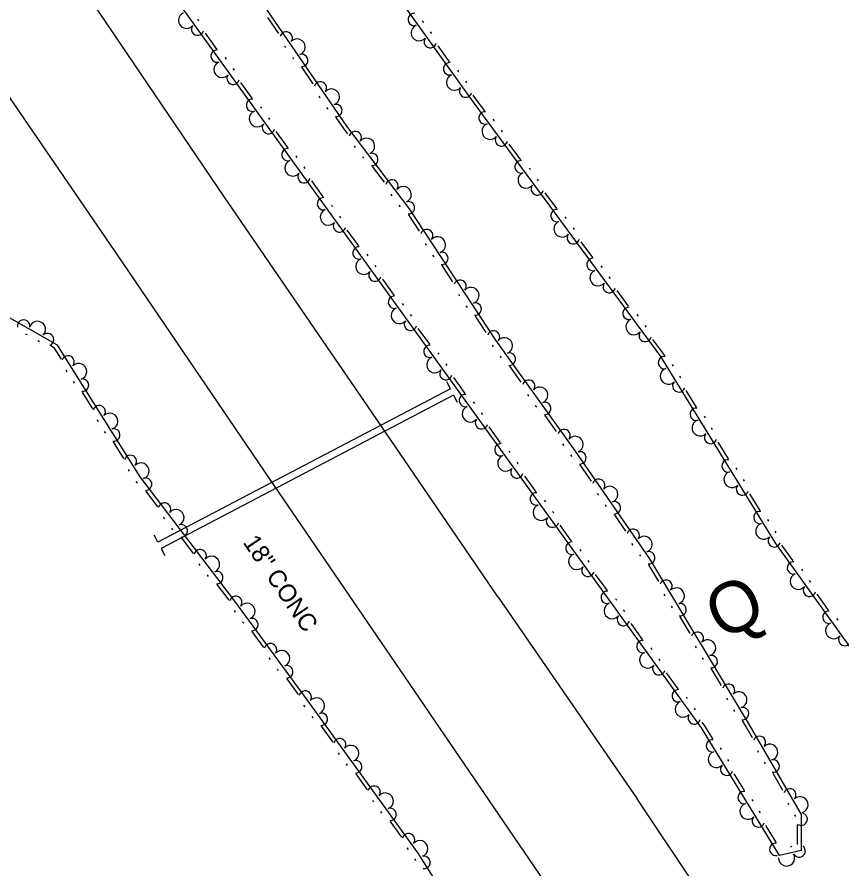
# Model space of a CAD drawing. Extents: x 2030130 to 2036320, y 723205 to 762423.
# Drawn here: x 2033217 to 2033389.9, y 761306.1 to 761484.7 of the extents above; entities that cross this region are included whole.
import ezdxf

# ---------------------------------------------------------------- set-up
doc = ezdxf.new("R2010")
doc.units = 0
for name, color, linetype in [('Draft_Station Labels Major', 7, 'Continuous'), ('Draft_Station Tics Major', 7, 'Continuous'), ('Draft_Station Tics Minor', 7, 'Continuous'), ('Old_Level_15', 7, 'Continuous'), ('Old_Level_26', 7, 'Continuous')]:
    doc.layers.add(name, color=color, linetype=linetype)

msp = doc.modelspace()

# ---------------------------------------------------------------- linework, layer by layer
at = {"layer": 'Draft_Station Labels Major'}
for p, q in [((2033317.86, 761363.04), (2033346.96, 761320.77)), ((2033297.27, 761347.85), (2033325.26, 761306.74))]:
    msp.add_line(p, q, dxfattribs=at)
for points in [[(2033317.86, 761363.04), (2033290.43, 761403.19), (2033260.47, 761446.88), (2033232.75, 761487.83), (2033204.6, 761528.87), (2033176.73, 761570.42), (2033148.96, 761611.47), (2033120.54, 761652.92), (2033093.45, 761693.44), (2033064.45, 761735.88), (2033037.38, 761775.77), (2033009.06, 761817.74)], [(2032987.95, 761803.12), (2033043.65, 761720.79), (2033056.64, 761702.34), (2033057.8, 761696.58), (2033076.72, 761668.89), (2033082.75, 761662.9), (2033099.45, 761638.44), (2033127.47, 761597.33), (2033155.33, 761556.18), (2033183.52, 761515.12), (2033211.27, 761473.78), (2033239.33, 761432.83), (2033268.78, 761389.51), (2033297.27, 761347.85)], [(2033712.22, 760786.66), (2033683.84, 760828.02), (2033655.87, 760868.99), (2033628.83, 760908.43), (2033600.16, 760950.82), (2033571.79, 760992.23), (2033543.75, 761033.03), (2033515.6, 761074.29), (2033487.47, 761115.18), (2033459.15, 761156.4), (2033430.9, 761197.59), (2033402.93, 761238.74), (2033380.71, 761271.71), (2033360.2, 761301.06), (2033346.96, 761320.77)], [(2033325.26, 761306.74), (2033353.27, 761265.49), (2033381.46, 761224.47), (2033409.65, 761183.47), (2033437.67, 761142.45), (2033465.74, 761101.32), (2033493.99, 761060.24), (2033522.13, 761019.11), (2033550.25, 760977.98), (2033578.36, 760936.85), (2033606.28, 760895.5), (2033634.33, 760854.29), (2033662.48, 760813.18), (2033690.27, 760771.87)]]:
    msp.add_lwpolyline(points, dxfattribs=at)
at = {"layer": 'Draft_Station Tics Major'}
for points in [[(2033068.77, 761781.86), (2033086.33, 761752.31), (2033109.9, 761713.34), (2033142.91, 761665.44), (2033169.42, 761629.65), (2033193.38, 761594), (2033213.28, 761565.74), (2033225.71, 761547.14), (2033246.82, 761520.6), (2033267.65, 761488.73), (2033286.08, 761461.77), (2033299.18, 761444.47), (2033317.3, 761416.96), (2033333.98, 761393.69), (2033349.54, 761371.11), (2033370.47, 761336.34), (2033381.34, 761317.53), (2033381.31, 761309.98), (2033376.82, 761308.9), (2033360.46, 761335.66), (2033268.79, 761462.78), (2033184.77, 761579.48), (2033107.4, 761688.4), (2033049.51, 761771.21)], [(2033399.47, 761341.65), (2033376.06, 761374.31), (2033351.9, 761413.52), (2033313, 761466.36), (2033285.32, 761505.1)], [(2033255.14, 761483.84), (2033254.9, 761484.18)], [(2033269.5, 761484.57), (2033271.81, 761481.18)], [(2033302.24, 761483.54), (2033302, 761483.87)], [(2033258.88, 761477.95), (2033256.49, 761481.27)], [(2033303.91, 761481.2), (2033303.67, 761481.54)], [(2033273.09, 761478.58), (2033273.33, 761478.24)], [(2033307.63, 761475.29), (2033305.24, 761478.63)], [(2033260.89, 761475.86), (2033260.65, 761476.19)], [(2033274.71, 761476.21), (2033274.95, 761475.87)], [(2033262.57, 761473.53), (2033262.33, 761473.86)], [(2033276.67, 761474.07), (2033278.99, 761470.69)], [(2033309.63, 761473.2), (2033309.39, 761473.53)], [(2033266.31, 761467.63), (2033263.92, 761470.96)], [(2033311.3, 761470.86), (2033311.06, 761471.19)], [(2033280.27, 761468.09), (2033280.5, 761467.75)], [(2033315.04, 761464.98), (2033313.67, 761466.84), (2033312.63, 761468.29)], [(2033268.32, 761465.54), (2033268.08, 761465.87)], [(2033281.89, 761465.72), (2033282.12, 761465.38)], [(2033270, 761463.21), (2033269.79, 761463.5), (2033269.76, 761463.54)], [(2033283.85, 761463.58), (2033285.41, 761461.29), (2033286.24, 761460.2)], [(2033317.07, 761462.91), (2033316.83, 761463.24)], [(2033273.74, 761457.32), (2033271.34, 761460.64)], [(2033318.77, 761460.6), (2033318.53, 761460.93)], [(2033287.65, 761457.66), (2033287.89, 761457.33)], [(2033322.58, 761454.74), (2033320.15, 761458.04)], [(2033275.75, 761455.23), (2033275.52, 761455.56)], [(2033289.38, 761455.37), (2033289.63, 761455.05)], [(2033277.43, 761452.9), (2033277.19, 761453.23)], [(2033291.44, 761453.33), (2033293.92, 761450.06)], [(2033324.61, 761452.67), (2033324.37, 761453)], [(2033281.18, 761447), (2033278.78, 761450.33)], [(2033326.31, 761450.36), (2033326.07, 761450.69)], [(2033295.32, 761447.53), (2033295.57, 761447.2)], [(2033330.11, 761444.5), (2033327.68, 761447.8)], [(2033283.19, 761444.92), (2033282.95, 761445.25)], [(2033297.06, 761445.24), (2033297.3, 761444.91)], [(2033299.03, 761443.21), (2033301.29, 761439.78)], [(2033284.87, 761442.59), (2033284.63, 761442.92)], [(2033332.15, 761442.43), (2033331.9, 761442.76)], [(2033288.62, 761436.69), (2033286.22, 761440.02)], [(2033333.85, 761440.12), (2033333.61, 761440.45)], [(2033302.53, 761437.16), (2033302.75, 761436.82)], [(2033337.65, 761434.26), (2033335.22, 761437.57)], [(2033290.63, 761434.6), (2033290.39, 761434.94)], [(2033304.11, 761434.76), (2033304.33, 761434.42)], [(2033292.31, 761432.27), (2033292.07, 761432.61)], [(2033306.03, 761432.59), (2033308.28, 761429.17)], [(2033339.68, 761432.19), (2033339.44, 761432.53)], [(2033296.05, 761426.38), (2033293.65, 761429.71)], [(2033341.39, 761429.88), (2033341.14, 761430.21)], [(2033345.19, 761424.03), (2033342.76, 761427.33)], [(2033309.52, 761426.54), (2033309.75, 761426.2)], [(2033298.06, 761424.29), (2033297.82, 761424.62)], [(2033311.1, 761424.14), (2033311.33, 761423.8)], [(2033373.93, 761191.17), (2033356.73, 761221.91), (2033337.95, 761251.98), (2033321.33, 761277.24), (2033301.07, 761309.44), (2033278.03, 761341.3), (2033262.68, 761362.2), (2033242.79, 761388.29), (2033225.48, 761415.9), (2033212.95, 761422.98)], [(2033299.74, 761421.96), (2033299.5, 761422.3)], [(2033313.02, 761421.97), (2033315.28, 761418.55)], [(2033347.22, 761421.96), (2033346.98, 761422.29)], [(2033348.92, 761419.65), (2033348.68, 761419.98)], [(2033219.23, 761418.02), (2033218.87, 761418.22)], [(2033303.49, 761416.07), (2033301.09, 761419.4)], [(2033221.72, 761416.61), (2033221.37, 761416.81)], [(2033352.75, 761413.72), (2033352.59, 761413.98), (2033350.29, 761417.09)], [(2033226.35, 761412.97), (2033224.9, 761415.29), (2033224.07, 761415.76)], [(2033316.56, 761415.9), (2033316.79, 761415.56)], [(2033305.5, 761413.98), (2033305.26, 761414.31)], [(2033318.23, 761413.56), (2033318.47, 761413.23)], [(2033307.18, 761411.65), (2033306.94, 761411.98)], [(2033320.23, 761411.47), (2033322.62, 761408.13)], [(2033354.6, 761411.49), (2033354.39, 761411.84)], [(2033227.53, 761410.32), (2033227.31, 761410.67)], [(2033356.11, 761409.05), (2033355.89, 761409.4)], [(2033229.05, 761407.89), (2033228.83, 761408.24)], [(2033310.92, 761405.76), (2033308.53, 761409.08)], [(2033232.89, 761402.55), (2033230.71, 761406.02)], [(2033359.41, 761402.9), (2033357.26, 761406.39)], [(2033312.93, 761403.67), (2033312.69, 761404)], [(2033323.96, 761405.56), (2033324.2, 761405.23)], [(2033325.63, 761403.23), (2033325.87, 761402.89)], [(2033234.06, 761399.9), (2033233.84, 761400.25)], [(2033314.61, 761401.34), (2033314.37, 761401.67)], [(2033327.64, 761401.13), (2033330.03, 761397.8)], [(2033361.27, 761400.67), (2033361.05, 761401.02)], [(2033318.36, 761395.45), (2033315.96, 761398.77)], [(2033362.77, 761398.22), (2033362.56, 761398.57)], [(2033235.59, 761397.46), (2033235.37, 761397.81)], [(2033239.42, 761392.12), (2033237.24, 761395.6)], [(2033331.36, 761395.23), (2033331.6, 761394.89)], [(2033366.08, 761392.07), (2033363.93, 761395.56)], [(2033320.37, 761393.36), (2033320.13, 761393.69)], [(2033322.05, 761391.03), (2033321.81, 761391.36)], [(2033333.02, 761392.91), (2033333.25, 761392.57)], [(2033240.6, 761389.47), (2033240.38, 761389.82)], [(2033334.99, 761390.78), (2033337.32, 761387.4)], [(2033367.94, 761389.84), (2033367.72, 761390.19)], [(2033325.8, 761385.13), (2033323.4, 761388.46)], [(2033369.44, 761387.4), (2033369.23, 761387.75)], [(2033242.24, 761386.99), (2033241.99, 761387.31)], [(2033246.54, 761382.02), (2033244.06, 761385.28)], [(2033338.61, 761384.81), (2033338.84, 761384.47)], [(2033372.75, 761381.25), (2033370.6, 761384.74)], [(2033327.81, 761383.05), (2033327.57, 761383.38)], [(2033340.24, 761382.44), (2033340.47, 761382.1)], [(2033329.49, 761380.72), (2033329.25, 761381.05)], [(2033247.96, 761379.48), (2033247.71, 761379.81)], [(2033342.2, 761380.31), (2033344.53, 761376.93)], [(2033374.6, 761379.02), (2033374.39, 761379.37)], [(2033249.7, 761377.2), (2033249.45, 761377.53)], [(2033333.23, 761374.82), (2033330.83, 761378.15)], [(2033254, 761372.23), (2033251.52, 761375.49)], [(2033376.11, 761376.58), (2033375.89, 761376.92)], [(2033345.82, 761374.34), (2033346.05, 761374)], [(2033379.68, 761370.67), (2033377.29, 761374)], [(2033335.25, 761372.73), (2033335.01, 761373.07)], [(2033347.45, 761371.97), (2033347.68, 761371.64)], [(2033255.42, 761369.7), (2033255.17, 761370.03)], [(2033336.92, 761370.4), (2033336.68, 761370.74)], [(2033349.34, 761369.85), (2033351.46, 761366.34)], [(2033381.69, 761368.57), (2033381.45, 761368.91)], [(2033257.16, 761367.42), (2033256.91, 761367.74)], [(2033340.67, 761364.51), (2033338.27, 761367.84)], [(2033383.36, 761366.24), (2033383.12, 761366.57)], [(2033261.46, 761362.45), (2033258.97, 761365.71)], [(2033342.68, 761362.42), (2033342.44, 761362.75)], [(2033352.58, 761363.67), (2033352.8, 761363.32)], [(2033387.09, 761360.33), (2033384.7, 761363.67)], [(2033354.07, 761361.21), (2033354.28, 761360.86)], [(2033262.83, 761359.91), (2033262.59, 761360.24)], [(2033344.36, 761360.09), (2033344.12, 761360.43)], [(2033264.53, 761357.6), (2033264.29, 761357.93)], [(2033348.1, 761354.2), (2033345.71, 761357.53)], [(2033355.9, 761358.96), (2033358.01, 761355.45)], [(2033389.09, 761358.24), (2033388.85, 761358.57)], [(2033268.75, 761352.55), (2033266.32, 761355.86)], [(2033350.12, 761352.11), (2033349.88, 761352.44)], [(2033359.14, 761352.78), (2033359.35, 761352.43)], [(2033270.12, 761349.99), (2033269.87, 761350.33)], [(2033360.62, 761350.32), (2033360.83, 761349.97)], [(2033351.8, 761349.78), (2033351.55, 761350.12)], [(2033271.82, 761347.68), (2033271.57, 761348.01)], [(2033355.54, 761343.89), (2033353.14, 761347.21)], [(2033362.45, 761348.07), (2033364.57, 761344.56)], [(2033276.03, 761342.64), (2033273.6, 761345.94)], [(2033357.55, 761341.8), (2033357.31, 761342.13)], [(2033365.7, 761341.89), (2033365.91, 761341.53)], [(2033277.39, 761340.08), (2033277.15, 761340.42)], [(2033359.23, 761339.47), (2033358.99, 761339.8)], [(2033279.07, 761337.76), (2033278.83, 761338.09)], [(2033367.18, 761339.43), (2033367.39, 761339.08)], [(2033283.25, 761332.68), (2033280.85, 761336)], [(2033362.81, 761333.39), (2033361.15, 761336.12), (2033360.58, 761336.9)], [(2033369.01, 761337.18), (2033369.77, 761335.93), (2033371.08, 761333.65)], [(2033364.66, 761331.15), (2033364.45, 761331.5)], [(2033372.16, 761330.96), (2033372.36, 761330.61)], [(2033284.6, 761330.11), (2033284.36, 761330.45)], [(2033366.16, 761328.71), (2033365.94, 761329.06)], [(2033286.28, 761327.79), (2033286.04, 761328.12)], [(2033373.59, 761328.48), (2033373.8, 761328.12)], [(2033290.46, 761322.71), (2033288.06, 761326.03)], [(2033369.44, 761322.54), (2033367.3, 761326.04)], [(2033375.39, 761326.2), (2033377.44, 761322.65)], [(2033291.81, 761320.15), (2033291.57, 761320.48)], [(2033371.29, 761320.31), (2033371.08, 761320.66)], [(2033378.52, 761319.95), (2033378.72, 761319.6)], [(2033293.49, 761317.82), (2033293.25, 761318.15)], [(2033372.79, 761317.86), (2033372.57, 761318.21)], [(2033379.95, 761317.47), (2033380.16, 761317.11)], [(2033297.67, 761312.74), (2033295.27, 761316.07)], [(2033376.07, 761311.7), (2033373.93, 761315.2)], [(2033380.51, 761315.3), (2033380.5, 761311.2)], [(2033299.02, 761310.18), (2033298.78, 761310.51)], [(2033379.42, 761310.79), (2033379.02, 761310.69)], [(2033300.6, 761307.88), (2033300.38, 761308.22)]]:
    msp.add_lwpolyline(points, dxfattribs=at)
for centre, radius, start, end in [((2033252.52, 761483.98), 1.69, 111.7161, 319.7886), ((2033300.28, 761484.16), 1.3, 86.3189, 287.1155), ((2033254.86, 761482.13), 1.3, 144.1873, 344.9839), ((2033301.29, 761481.35), 1.69, 111.5142, 319.5867), ((2033273.42, 761480.29), 1.3, 322.7904, 163.5869), ((2033275.71, 761478.38), 1.69, 290.3192, 138.3917), ((2033303.62, 761479.49), 1.3, 143.9854, 344.7819), ((2033258.94, 761476.47), 1.3, 86.5208, 287.3174), ((2033259.95, 761473.66), 1.69, 111.7161, 319.7886), ((2033276.66, 761475.55), 1.3, 265.1239, 105.9205), ((2033307.68, 761473.82), 1.3, 86.3189, 287.1155), ((2033262.29, 761471.81), 1.3, 144.1873, 344.9839), ((2033308.68, 761471), 1.69, 111.5142, 319.5867), ((2033280.59, 761469.8), 1.3, 322.7904, 163.5869), ((2033311.01, 761469.14), 1.3, 143.9854, 344.7819), ((2033282.89, 761467.89), 1.69, 290.3192, 138.3917), ((2033266.36, 761466.15), 1.3, 86.5208, 287.3174), ((2033283.83, 761465.06), 1.3, 265.1239, 105.9205), ((2033267.38, 761463.34), 1.69, 111.7161, 319.7886), ((2033315.11, 761463.5), 1.3, 87.1294, 287.926), ((2033269.72, 761461.49), 1.3, 144.2321, 345.0287), ((2033316.15, 761460.7), 1.69, 112.3247, 320.3972), ((2033287.88, 761459.39), 1.3, 325.5863, 166.3829), ((2033290.27, 761457.59), 1.69, 293.1152, 141.1876), ((2033318.51, 761458.88), 1.3, 144.7959, 345.5925), ((2033273.8, 761455.84), 1.3, 86.5657, 287.3622), ((2033291.35, 761454.81), 1.3, 267.9199, 108.7164), ((2033274.81, 761453.03), 1.69, 111.7609, 319.8334), ((2033322.65, 761453.26), 1.3, 87.1294, 287.926), ((2033323.69, 761450.46), 1.69, 112.3247, 320.3972), ((2033277.16, 761451.18), 1.3, 144.2321, 345.0287), ((2033295.56, 761449.25), 1.3, 325.5863, 166.3829), ((2033297.95, 761447.46), 1.69, 293.1152, 141.1876), ((2033326.05, 761448.64), 1.3, 144.7959, 345.5925), ((2033281.23, 761445.53), 1.3, 86.5657, 287.3622), ((2033299.03, 761444.68), 1.3, 267.9199, 108.7164), ((2033282.25, 761442.72), 1.69, 111.7609, 319.8334), ((2033330.18, 761443.03), 1.3, 87.1294, 287.926), ((2033284.59, 761440.87), 1.3, 144.2321, 345.0287), ((2033331.22, 761440.23), 1.69, 112.3247, 320.3972), ((2033302.88, 761438.86), 1.3, 321.8089, 162.6054), ((2033305.14, 761436.92), 1.69, 289.3377, 137.4102), ((2033333.59, 761438.4), 1.3, 144.7959, 345.5925), ((2033288.67, 761435.21), 1.3, 86.5657, 287.3622), ((2033306.04, 761434.07), 1.3, 264.1424, 104.939), ((2033289.68, 761432.41), 1.69, 111.7609, 319.8334), ((2033337.72, 761432.79), 1.3, 87.1294, 287.926), ((2033292.03, 761430.56), 1.3, 144.2321, 345.0287), ((2033338.76, 761429.99), 1.69, 112.3247, 320.3972), ((2033309.87, 761428.25), 1.3, 321.8089, 162.6054), ((2033341.12, 761428.16), 1.3, 144.7959, 345.5925), ((2033312.14, 761426.3), 1.69, 289.3377, 137.4102), ((2033296.11, 761424.9), 1.3, 86.5657, 287.3622), ((2033297.12, 761422.09), 1.69, 111.7609, 319.8334), ((2033313.03, 761423.45), 1.3, 264.1424, 104.939), ((2033345.26, 761422.55), 1.3, 87.1294, 287.926), ((2033218.4, 761419.9), 1.3, 348.9505, 189.7471), ((2033221.3, 761419.2), 1.69, 316.4793, 164.5518), ((2033299.46, 761420.25), 1.3, 144.2321, 345.0287), ((2033346.3, 761419.75), 1.69, 112.3247, 320.3972), ((2033223.4, 761417.07), 1.3, 291.2841, 132.0806), ((2033316.87, 761417.63), 1.3, 321.8089, 162.6054), ((2033348.66, 761417.93), 1.3, 144.7959, 345.5925), ((2033319.18, 761415.76), 1.69, 291.5846, 139.6571), ((2033303.54, 761414.59), 1.3, 86.5657, 287.3622), ((2033227.7, 761412.36), 1.3, 320.5276, 161.3242), ((2033304.56, 761411.78), 1.69, 111.7609, 319.8334), ((2033320.18, 761412.95), 1.3, 266.3894, 107.1859), ((2033352.69, 761412.24), 1.3, 82.4032, 283.1998), ((2033229.92, 761410.37), 1.69, 288.0564, 136.1289), ((2033353.5, 761409.37), 1.69, 107.5985, 315.671), ((2033306.9, 761409.93), 1.3, 144.2321, 345.0287), ((2033230.75, 761407.5), 1.3, 262.8612, 103.6577), ((2033324.24, 761407.28), 1.3, 324.0558, 164.8524), ((2033355.7, 761407.35), 1.3, 140.0697, 340.8662), ((2033326.58, 761405.42), 1.69, 291.5846, 139.6571), ((2033310.98, 761404.28), 1.3, 86.5657, 287.3622), ((2033327.59, 761402.61), 1.3, 266.3894, 107.1859), ((2033234.23, 761401.94), 1.3, 320.5276, 161.3242), ((2033311.99, 761401.47), 1.69, 111.7609, 319.8334), ((2033359.36, 761401.42), 1.3, 82.4032, 283.1998), ((2033236.45, 761399.94), 1.69, 288.0564, 136.1289), ((2033314.34, 761399.62), 1.3, 144.2321, 345.0287), ((2033360.17, 761398.54), 1.69, 107.5985, 315.671), ((2033237.28, 761397.08), 1.3, 262.8612, 103.6577), ((2033331.65, 761396.94), 1.3, 324.0558, 164.8524), ((2033333.99, 761395.09), 1.69, 291.5846, 139.6571), ((2033362.37, 761396.53), 1.3, 140.0697, 340.8662), ((2033318.41, 761393.97), 1.3, 86.5657, 287.3622), ((2033334.97, 761392.26), 1.3, 265.3423, 106.1389), ((2033240.77, 761391.52), 1.3, 320.5276, 161.3242), ((2033319.43, 761391.16), 1.69, 111.7609, 319.8334), ((2033366.03, 761390.59), 1.3, 82.4032, 283.1998), ((2033242.99, 761389.52), 1.69, 288.0564, 136.1289), ((2033321.77, 761389.31), 1.3, 144.2321, 345.0287), ((2033243.96, 761386.75), 1.3, 268.0802, 108.8768), ((2033338.92, 761386.52), 1.3, 323.0088, 163.8053), ((2033366.84, 761387.72), 1.69, 107.5985, 315.671), ((2033341.23, 761384.62), 1.69, 290.5376, 138.6101), ((2033369.04, 761385.71), 1.3, 140.0697, 340.8662), ((2033325.85, 761383.66), 1.3, 86.5657, 287.3622), ((2033247.94, 761381.53), 1.3, 325.7467, 166.5432), ((2033326.86, 761380.85), 1.69, 111.7609, 319.8334), ((2033342.18, 761381.79), 1.3, 265.3423, 106.1389), ((2033250.33, 761379.75), 1.69, 293.2755, 141.348), ((2033372.7, 761379.77), 1.3, 82.4032, 283.1998), ((2033329.21, 761379), 1.3, 144.2321, 345.0287), ((2033251.42, 761376.97), 1.3, 268.0802, 108.8768), ((2033346.14, 761376.05), 1.3, 323.0088, 163.8053), ((2033373.5, 761376.9), 1.69, 107.5985, 315.671), ((2033348.44, 761374.15), 1.69, 290.5376, 138.6101), ((2033375.71, 761374.88), 1.3, 140.0697, 340.8662), ((2033333.29, 761373.34), 1.3, 86.5657, 287.3622), ((2033255.4, 761371.75), 1.3, 325.7467, 166.5432), ((2033334.3, 761370.54), 1.69, 111.7609, 319.8334), ((2033349.39, 761371.32), 1.3, 265.3423, 106.1389), ((2033257.79, 761369.96), 1.69, 293.2755, 141.348), ((2033379.73, 761369.19), 1.3, 86.4005, 287.1971), ((2033258.88, 761367.18), 1.3, 268.0802, 108.8768), ((2033336.65, 761368.69), 1.3, 144.2321, 345.0287), ((2033353, 761365.36), 1.3, 319.4851, 160.2817), ((2033380.74, 761366.38), 1.69, 111.5958, 319.6683), ((2033355.19, 761363.32), 1.69, 287.0139, 135.0864), ((2033383.08, 761364.52), 1.3, 144.067, 344.8635), ((2033262.85, 761361.96), 1.3, 324.733, 165.5296), ((2033340.72, 761363.03), 1.3, 86.5657, 287.3622), ((2033265.21, 761360.13), 1.69, 292.2618, 140.3343), ((2033341.74, 761360.22), 1.69, 111.7609, 319.8334), ((2033355.97, 761360.44), 1.3, 261.8186, 102.6152), ((2033387.14, 761358.86), 1.3, 86.4005, 287.1971), ((2033266.25, 761357.33), 1.3, 267.0665, 107.8631), ((2033344.08, 761358.38), 1.3, 144.2321, 345.0287), ((2033388.14, 761356.04), 1.69, 111.5958, 319.6683), ((2033359.56, 761354.47), 1.3, 319.4851, 160.2817), ((2033348.16, 761352.72), 1.3, 86.5657, 287.3622), ((2033361.74, 761352.43), 1.69, 287.0139, 135.0864), ((2033390.48, 761354.19), 1.3, 144.067, 344.8635), ((2033270.14, 761352.04), 1.3, 324.733, 165.5296), ((2033272.5, 761350.22), 1.69, 292.2618, 140.3343), ((2033349.17, 761349.91), 1.69, 111.7609, 319.8334), ((2033362.52, 761349.55), 1.3, 261.8186, 102.6152), ((2033273.54, 761347.42), 1.3, 267.0665, 107.8631), ((2033351.52, 761348.06), 1.3, 144.2321, 345.0287), ((2033277.42, 761342.13), 1.3, 324.733, 165.5296), ((2033355.6, 761342.41), 1.3, 86.5657, 287.3622), ((2033366.12, 761343.57), 1.3, 319.4851, 160.2817), ((2033368.3, 761341.54), 1.69, 287.0139, 135.0864), ((2033279.77, 761340.29), 1.69, 291.8387, 139.9112), ((2033356.61, 761339.6), 1.69, 111.7609, 319.8334), ((2033369.08, 761338.66), 1.3, 261.8186, 102.6152), ((2033280.79, 761337.48), 1.3, 266.6434, 107.44), ((2033358.95, 761337.75), 1.3, 144.2321, 345.0287), ((2033284.64, 761332.16), 1.3, 324.3099, 165.1065), ((2033362.75, 761331.91), 1.3, 82.2083, 283.0049), ((2033372.61, 761332.64), 1.3, 318.4451, 159.2417), ((2033286.98, 761330.32), 1.69, 291.8387, 139.9112), ((2033363.55, 761329.04), 1.69, 107.4036, 315.4761), ((2033374.76, 761330.57), 1.69, 285.9739, 134.0464), ((2033288, 761327.51), 1.3, 266.6434, 107.44), ((2033375.48, 761327.67), 1.3, 260.7787, 101.5752), ((2033365.75, 761327.01), 1.3, 139.8748, 340.6714), ((2033291.85, 761322.2), 1.3, 324.3099, 165.1065), ((2033294.19, 761320.35), 1.69, 291.8387, 139.9112), ((2033369.38, 761321.07), 1.3, 82.2083, 283.0049), ((2033378.97, 761321.63), 1.3, 318.4451, 159.2417), ((2033381.11, 761319.56), 1.69, 285.9739, 134.0464), ((2033295.21, 761317.54), 1.3, 266.6434, 107.44), ((2033370.18, 761318.19), 1.69, 107.4036, 315.4761), ((2033372.38, 761316.17), 1.3, 139.8748, 340.6714), ((2033381.34, 761316.53), 1.3, 230.5753, 71.3719), ((2033299.06, 761312.23), 1.3, 324.3099, 165.1065), ((2033301.4, 761310.38), 1.69, 291.8387, 139.9112), ((2033376.02, 761310.22), 1.3, 82.2083, 283.0049), ((2033378.3, 761308.41), 1.69, 179.5683, 27.6408), ((2033380.9, 761309.88), 1.3, 212.0395, 52.836), ((2033302.3, 761307.49), 1.3, 262.9382, 103.7347)]:
    msp.add_arc(centre, radius, start, end, dxfattribs=at)
at = {"layer": 'Draft_Station Tics Minor'}
for p, q in [((2033307.83, 761406.73), (2033307.06, 761408.19)), ((2033308.51, 761405.43), (2033309.27, 761403.97)), ((2033246.52, 761374.58), (2033245.76, 761376.04)), ((2033247.21, 761373.28), (2033247.97, 761371.82))]:
    msp.add_line(p, q, dxfattribs=at)
for points in [[(2033307.83, 761406.73), (2033246.52, 761374.58)], [(2033308.51, 761405.43), (2033247.21, 761373.28)]]:
    msp.add_lwpolyline(points, dxfattribs=at)

# ---------------------------------------------------------------- texts
at = {"layer": 'Old_Level_15'}
msp.add_text('Q', height=10.66, rotation=25.7434, dxfattribs=at).set_placement((2033364.63, 761353.88))
at = {"layer": 'Old_Level_26'}
msp.add_text('18" CONC', height=3.691, rotation=304.2403, dxfattribs=at).set_placement((2033264.24, 761374.55))

doc.saveas('drawing.dxf')
